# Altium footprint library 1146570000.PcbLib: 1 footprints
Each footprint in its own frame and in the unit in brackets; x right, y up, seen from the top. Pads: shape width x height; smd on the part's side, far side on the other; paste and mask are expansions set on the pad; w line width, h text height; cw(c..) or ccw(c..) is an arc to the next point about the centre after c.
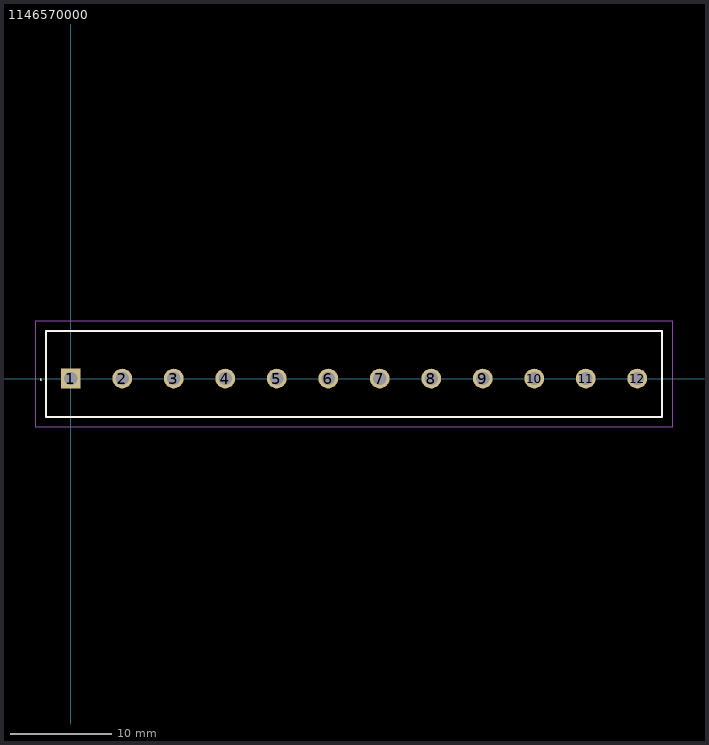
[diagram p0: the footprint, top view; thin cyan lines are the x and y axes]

## 1146570000 [mm]
pads (12):
  rect 1.95x1.95 hole 1.3: 1(0,0)
  round 1.95 hole 1.3: 2(5.08,0) 3(10.16,0) 4(15.24,0) 5(20.32,0) 6(25.4,0) 7(30.48,0) 8(35.56,0) 9(40.64,0) 10(45.72,0) 11(50.8,0) 12(55.88,0)
Top Overlay:
  lines w0.1: -3,-0.1 -3,-0.1 ; -3,-0.1 ccw(c-2.95,-0.1) -2.9,-0.1 ; -3,-0.1 cw(c-2.95,-0.1) -2.9,-0.1 ; -3,-0.1 -3,-0.1 ; -3,-0.1 ccw(c-2.95,-0.1) -2.9,-0.1 ; -2.9,-0.1 -2.9,-0.1
  lines w0.2: -2.2,-3.8 -2.44,-3.8 ; -2.44,-3.8 -2.44,4.7 58.32,4.7 58.32,-3.8 -2.44,-3.8
Mechanical 15:
  lines w0.1: -2.44,-3.8 58.32,-3.8 58.32,4.7 -2.44,4.7 -2.44,-3.8
Mechanical 20:
  lines w0.1: -3.44,-4.8 59.32,-4.8 59.32,5.7 -3.44,5.7 -3.44,-4.8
